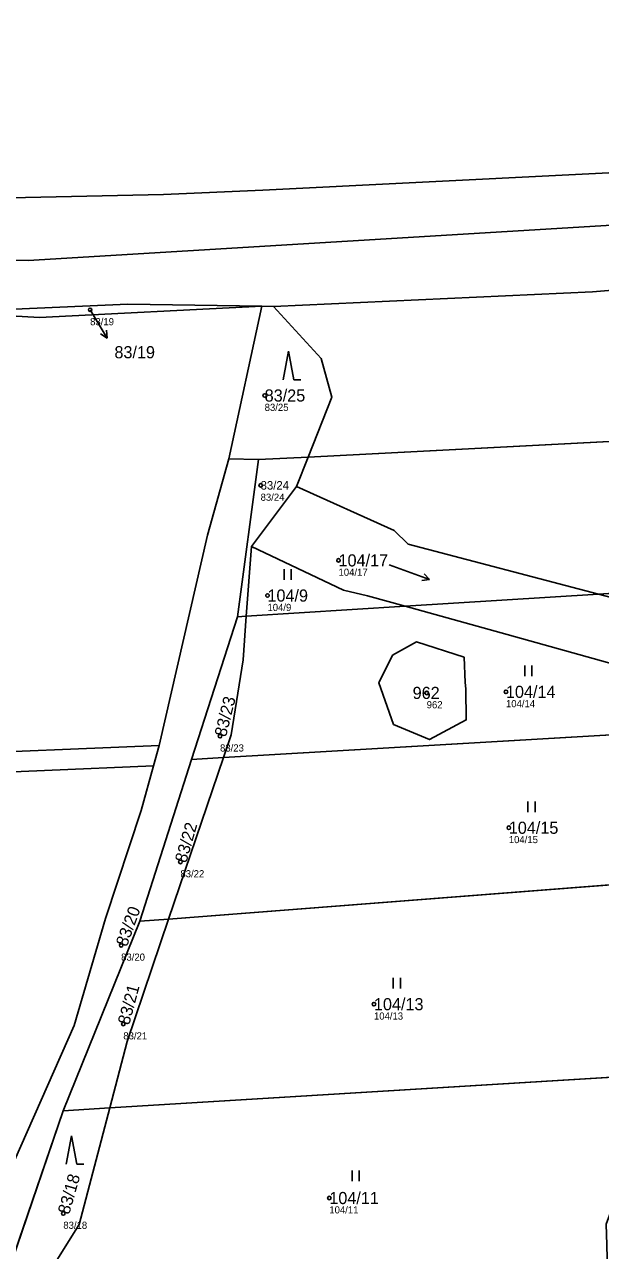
# Model space of a CAD drawing. Extents: x -734504 to -730695, y -1027923 to -1024502.
# Drawn here: x -731608.6 to -731527.8, y -1026155.5 to -1025983.6 of the extents above; entities that cross this region are included whole.
import ezdxf

# ---------------------------------------------------------------- set-up
doc = ezdxf.new("R2010")
doc.units = 0
for name, color, linetype in [('Definiční body', 7, 'Continuous'), ('Hranice parcel', 7, 'Continuous'), ('Parcelní čísla', 7, 'Continuous'), ('Polygon parcely', 7, 'Continuous'), ('Pop  PČ popisy', 7, 'Continuous'), ('Vnitřní kresba', 7, 'Continuous'), ('Značky kultur', 7, 'Continuous')]:
    doc.layers.add(name, color=color, linetype=linetype)

msp = doc.modelspace()

# ---------------------------------------------------------------- linework, layer by layer
at = {"layer": 'Definiční body'}
for centre in [(-731599.42, -1026023.65), (-731574.93, -1026035.66), (-731575.5, -1026048.26), (-731564.57, -1026058.78), (-731574.54, -1026063.71), (-731552.2, -1026077.36), (-731541.08, -1026077.21), (-731581.19, -1026083.42), (-731540.68, -1026096.27), (-731586.75, -1026101.06), (-731595.07, -1026112.75), (-731559.6, -1026121.01), (-731594.76, -1026123.79), (-731565.86, -1026148.19), (-731603.18, -1026150.35)]:
    msp.add_circle(centre, 0.25, dxfattribs=at)
at = {"layer": 'Hranice parcel'}
for p, q in [((-731579.95, -1026044.53), (-731575.33, -1026023.13)), ((-731575.33, -1026023.13), (-731573.67, -1026023.16)), ((-731568.83, -1026044.29), (-731476.12, -1026039.48)), ((-731575.78, -1026044.62), (-731579.95, -1026044.53)), ((-731578.73, -1026066.7), (-731575.78, -1026044.62)), ((-731568.83, -1026044.29), (-731575.78, -1026044.62)), ((-731570.47, -1026048.43), (-731568.83, -1026044.29)), ((-731576.8, -1026056.83), (-731570.47, -1026048.43)), ((-731577.51, -1026066.62), (-731576.8, -1026056.83)), ((-731528.11, -1026063.51), (-731466.76, -1026059.77)), ((-731528.11, -1026063.51), (-731555.24, -1026065.22)), ((-731577.51, -1026066.62), (-731555.24, -1026065.22)), ((-731585.19, -1026086.68), (-731578.73, -1026066.7)), ((-731577.51, -1026066.62), (-731578.73, -1026066.7)), ((-731577.96, -1026072.72), (-731577.51, -1026066.62)), ((-731579.64, -1026083.26), (-731577.96, -1026072.72)), ((-731580.71, -1026086.42), (-731482.31, -1026080.69)), ((-731580.71, -1026086.42), (-731579.64, -1026083.26)), ((-731590.53, -1026087.6), (-731589.71, -1026084.72)), ((-731592.44, -1026109.38), (-731585.19, -1026086.68)), ((-731588.4, -1026109.07), (-731580.71, -1026086.42)), ((-731580.71, -1026086.42), (-731585.19, -1026086.68)), ((-731506.7, -1026102.73), (-731588.4, -1026109.07)), ((-731603.21, -1026135.95), (-731592.44, -1026109.38)), ((-731594.22, -1026126.22), (-731588.4, -1026109.07)), ((-731588.4, -1026109.07), (-731592.44, -1026109.38)), ((-731596.66, -1026135.55), (-731594.22, -1026126.22)), ((-731519.15, -1026130.8), (-731596.66, -1026135.55)), ((-731596.66, -1026135.55), (-731603.21, -1026135.95)), ((-731603.21, -1026135.95), (-731612.63, -1026163.52))]:
    msp.add_line(p, q, dxfattribs=at)
for points in [[(-731897.94, -1025983.64), (-731862.07, -1025991.44), (-731847.22, -1025994.8), (-731827.82, -1025997.98), (-731799.13, -1026001.29), (-731775.22, -1026003.63), (-731763.84, -1026004.82), (-731742.5, -1026007.73), (-731730.75, -1026008.23), (-731698.59, -1026008.86), (-731662.59, -1026008.85), (-731619.31, -1026008.12), (-731589.11, -1026007.48), (-731575.19, -1026006.86), (-731508.93, -1026003.54), (-731470.15, -1026002.29), (-731442.98, -1026001.65), (-731406.79, -1026000.22), (-731383.28, -1026000.92)], [(-731473.47, -1026018.47), (-731481.39, -1026018.12), (-731500.93, -1026018.8), (-731528.93, -1026021.11), (-731573.67, -1026023.16)], [(-731619.6, -1026023.97), (-731594.13, -1026022.85), (-731575.33, -1026023.13)], [(-731575.33, -1026023.13), (-731606.51, -1026024.73), (-731619.6, -1026023.97)], [(-731573.67, -1026023.16), (-731567.02, -1026030.49), (-731565.51, -1026035.89), (-731568.83, -1026044.29)], [(-731589.71, -1026084.72), (-731582.94, -1026055.26), (-731579.95, -1026044.53)], [(-731528.11, -1026063.51), (-731554.81, -1026056.52), (-731556.78, -1026054.6), (-731570.47, -1026048.43)], [(-731555.24, -1026065.22), (-731560.52, -1026063.77), (-731563.87, -1026062.97), (-731576.8, -1026056.83)], [(-731471.3, -1026065.92), (-731479.74, -1026067.1), (-731492.82, -1026066.79), (-731519.69, -1026065.71), (-731528.11, -1026063.51)], [(-731555.24, -1026065.22), (-731541.77, -1026068.92), (-731524.83, -1026073.68), (-731511.48, -1026075.37), (-731503.25, -1026074.97), (-731482.31, -1026080.69)], [(-731546.8, -1026075.89), (-731546.95, -1026072.37), (-731553.62, -1026070.22), (-731556.98, -1026072.08), (-731558.92, -1026075.95), (-731556.85, -1026081.78), (-731551.82, -1026083.9), (-731546.64, -1026081.15), (-731546.71, -1026076.77), (-731546.8, -1026075.89)], [(-731589.71, -1026084.72), (-731621.46, -1026086.04), (-731697.6, -1026088.85), (-731731.22, -1026090.36)], [(-731590.53, -1026087.6), (-731621.14, -1026088.91), (-731698.05, -1026092.16), (-731731.15, -1026093.41)], [(-731630.9, -1026187.05), (-731624.84, -1026175.76), (-731612.94, -1026149.38), (-731601.66, -1026124.02), (-731597.25, -1026108.98), (-731592.25, -1026093.83), (-731590.53, -1026087.6)], [(-731608.08, -1026163.26), (-731600.95, -1026151.92), (-731596.66, -1026135.55)]]:
    msp.add_lwpolyline(points, dxfattribs=at)
at = {"layer": 'Polygon parcely'}
for points in [[(-731383.28, -1026000.92), (-731406.79, -1026000.22), (-731442.98, -1026001.65), (-731470.15, -1026002.29), (-731508.93, -1026003.54), (-731575.19, -1026006.86), (-731589.11, -1026007.48), (-731619.31, -1026008.12), (-731662.59, -1026008.85), (-731698.59, -1026008.86), (-731730.75, -1026008.23), (-731742.5, -1026007.73), (-731763.84, -1026004.82), (-731775.22, -1026003.63), (-731799.13, -1026001.29), (-731827.82, -1025997.98), (-731847.22, -1025994.8), (-731862.07, -1025991.44), (-731897.94, -1025983.64)], [(-731897.94, -1025983.64), (-731862.07, -1025991.44), (-731847.22, -1025994.8), (-731827.82, -1025997.98), (-731799.13, -1026001.29), (-731775.22, -1026003.63), (-731763.84, -1026004.82), (-731742.5, -1026007.73), (-731730.75, -1026008.23), (-731698.59, -1026008.86), (-731662.59, -1026008.85), (-731619.31, -1026008.12), (-731589.11, -1026007.48), (-731575.19, -1026006.86), (-731508.93, -1026003.54), (-731470.15, -1026002.29), (-731442.98, -1026001.65), (-731406.79, -1026000.22), (-731383.28, -1026000.92)], [(-731727.03, -1026023.83), (-731716.21, -1026023.81), (-731698.55, -1026023.77), (-731659.65, -1026023.51), (-731619.6, -1026023.97), (-731594.13, -1026022.85), (-731575.33, -1026023.13), (-731573.67, -1026023.16), (-731528.93, -1026021.11), (-731500.93, -1026018.8), (-731481.39, -1026018.12), (-731473.47, -1026018.47), (-731471.55, -1026018.36), (-731469.07, -1026018.22), (-731461.25, -1026017.78), (-731449.48, -1026016.71), (-731442.63, -1026016.08), (-731416.63, -1026016), (-731350.25, -1026014.24)]]:
    msp.add_lwpolyline(points, dxfattribs=at)
for points in [[(-731565.51, -1026035.89), (-731568.83, -1026044.29), (-731476.12, -1026039.48), (-731477.2, -1026037.15), (-731473.47, -1026018.47), (-731481.39, -1026018.12), (-731500.93, -1026018.8), (-731528.93, -1026021.11), (-731573.67, -1026023.16), (-731567.02, -1026030.49)], [(-731582.94, -1026055.26), (-731579.95, -1026044.53), (-731575.33, -1026023.13), (-731606.51, -1026024.73), (-731619.6, -1026023.97), (-731659.65, -1026023.51), (-731683.44, -1026026), (-731716.21, -1026023.81), (-731727.03, -1026023.83), (-731729.55, -1026023.95), (-731732.07, -1026023.98), (-731732.01, -1026034.57), (-731732.67, -1026049.28), (-731731.29, -1026087.21), (-731731.22, -1026090.36), (-731697.6, -1026088.85), (-731621.46, -1026086.04), (-731589.71, -1026084.72)], [(-731575.33, -1026023.13), (-731594.13, -1026022.85), (-731619.6, -1026023.97), (-731606.51, -1026024.73)], [(-731568.83, -1026044.29), (-731565.51, -1026035.89), (-731567.02, -1026030.49), (-731573.67, -1026023.16), (-731575.33, -1026023.13), (-731579.95, -1026044.53), (-731575.78, -1026044.62)], [(-731466.76, -1026059.77), (-731476.12, -1026039.48), (-731568.83, -1026044.29), (-731570.47, -1026048.43), (-731556.78, -1026054.6), (-731554.81, -1026056.52), (-731528.11, -1026063.51)], [(-731579.95, -1026044.53), (-731582.94, -1026055.26), (-731589.71, -1026084.72), (-731590.53, -1026087.6), (-731592.25, -1026093.83), (-731597.25, -1026108.98), (-731601.66, -1026124.02), (-731612.94, -1026149.38), (-731624.84, -1026175.76), (-731630.9, -1026187.05), (-731626.73, -1026188.13), (-731621.32, -1026178.95), (-731612.63, -1026163.52), (-731603.21, -1026135.95), (-731592.44, -1026109.38), (-731585.19, -1026086.68), (-731578.73, -1026066.7), (-731575.78, -1026044.62)], [(-731570.47, -1026048.43), (-731568.83, -1026044.29), (-731575.78, -1026044.62), (-731578.73, -1026066.7), (-731577.51, -1026066.62), (-731576.8, -1026056.83)], [(-731528.11, -1026063.51), (-731554.81, -1026056.52), (-731556.78, -1026054.6), (-731570.47, -1026048.43), (-731576.8, -1026056.83), (-731563.87, -1026062.97), (-731560.52, -1026063.77), (-731555.24, -1026065.22)], [(-731563.87, -1026062.97), (-731576.8, -1026056.83), (-731577.51, -1026066.62), (-731555.24, -1026065.22), (-731560.52, -1026063.77)], [(-731466.76, -1026059.77), (-731528.11, -1026063.51), (-731519.69, -1026065.71), (-731492.82, -1026066.79), (-731479.74, -1026067.1), (-731471.3, -1026065.92), (-731466.19, -1026061.01)], [(-731528.11, -1026063.51), (-731555.24, -1026065.22), (-731541.77, -1026068.92), (-731524.83, -1026073.68), (-731511.48, -1026075.37), (-731503.25, -1026074.97), (-731482.31, -1026080.69), (-731481.14, -1026080.63), (-731462.23, -1026074.08), (-731471.3, -1026065.92), (-731479.74, -1026067.1), (-731492.82, -1026066.79), (-731519.69, -1026065.71)], [(-731482.31, -1026080.69), (-731503.25, -1026074.97), (-731511.48, -1026075.37), (-731524.83, -1026073.68), (-731541.77, -1026068.92), (-731555.24, -1026065.22), (-731577.51, -1026066.62), (-731577.96, -1026072.72), (-731579.64, -1026083.26), (-731580.71, -1026086.42)], [(-731577.51, -1026066.62), (-731578.73, -1026066.7), (-731585.19, -1026086.68), (-731580.71, -1026086.42), (-731579.64, -1026083.26), (-731577.96, -1026072.72)], [(-731546.8, -1026075.89), (-731546.71, -1026076.77), (-731546.64, -1026081.15), (-731551.82, -1026083.9), (-731556.85, -1026081.78), (-731558.92, -1026075.95), (-731556.98, -1026072.08), (-731553.62, -1026070.22), (-731546.95, -1026072.37)], [(-731546.8, -1026075.89), (-731546.95, -1026072.37), (-731553.62, -1026070.22), (-731556.98, -1026072.08), (-731558.92, -1026075.95), (-731556.85, -1026081.78), (-731551.82, -1026083.9), (-731546.64, -1026081.15), (-731546.71, -1026076.77)], [(-731460.65, -1026079.08), (-731481.14, -1026080.63), (-731482.31, -1026080.69), (-731580.71, -1026086.42), (-731588.4, -1026109.07), (-731506.7, -1026102.73), (-731494.43, -1026093.08), (-731477.42, -1026087.59), (-731460.31, -1026080.16)], [(-731621.46, -1026086.04), (-731697.6, -1026088.85), (-731731.22, -1026090.36), (-731731.15, -1026093.41), (-731698.05, -1026092.16), (-731621.14, -1026088.91), (-731590.53, -1026087.6), (-731589.71, -1026084.72)], [(-731612.94, -1026149.38), (-731601.66, -1026124.02), (-731597.25, -1026108.98), (-731592.25, -1026093.83), (-731590.53, -1026087.6), (-731621.14, -1026088.91), (-731698.05, -1026092.16), (-731731.15, -1026093.41), (-731729.6, -1026159.46), (-731684.57, -1026173.9), (-731652.47, -1026184.25), (-731635.03, -1026188.69), (-731632.44, -1026189.52), (-731630.9, -1026187.05), (-731624.84, -1026175.76)], [(-731580.71, -1026086.42), (-731585.19, -1026086.68), (-731592.44, -1026109.38), (-731588.4, -1026109.07)], [(-731516.54, -1026115.92), (-731508.81, -1026104.39), (-731506.7, -1026102.73), (-731588.4, -1026109.07), (-731594.22, -1026126.22), (-731596.66, -1026135.55), (-731519.15, -1026130.8), (-731514.2, -1026117.57)], [(-731588.4, -1026109.07), (-731592.44, -1026109.38), (-731603.21, -1026135.95), (-731596.66, -1026135.55), (-731594.22, -1026126.22)], [(-731596.66, -1026135.55), (-731600.95, -1026151.92), (-731608.08, -1026163.26), (-731526.81, -1026158.57), (-731526.93, -1026154.74), (-731527.02, -1026151.87), (-731522.52, -1026139.82), (-731519.15, -1026130.8)], [(-731603.21, -1026135.95), (-731612.63, -1026163.52), (-731608.08, -1026163.26), (-731600.95, -1026151.92), (-731596.66, -1026135.55)]]:
    msp.add_lwpolyline(points, close=True, dxfattribs=at)
at = {"layer": 'Pop  PČ popisy'}
for p, q in [((-731599.42, -1026023.65), (-731598.57, -1026025.05)), ((-731598.57, -1026025.05), (-731597.02, -1026027.62)), ((-731597.02, -1026027.62), (-731597.97, -1026027.02)), ((-731597.02, -1026027.62), (-731597.11, -1026026.51))]:
    msp.add_line(p, q, dxfattribs=at)
at = {"layer": 'Vnitřní kresba'}
msp.add_lwpolyline([(-731739.28, -1026015), (-731608.1, -1026016.73), (-731451.32, -1026007.24), (-731364.57, -1026008.08), (-731305.14, -1026012.49), (-731265.75, -1026016.16), (-731249.68, -1026018.55), (-731220.78, -1026024.33), (-731170.26, -1026039.02), (-731127.3, -1026055.65), (-731100.51, -1026067.24), (-731081.11, -1026075.58), (-731070.69, -1026082.31), (-731018.8, -1026119.92), (-730984.01, -1026148.82)], dxfattribs=at)
at = {"layer": 'Značky kultur'}
for p, q in [((-731571.6, -1026029.46), (-731572.35, -1026033.46)), ((-731570.85, -1026033.46), (-731571.6, -1026029.46)), ((-731570.85, -1026033.46), (-731569.85, -1026033.46)), ((-731572.21, -1026061.51), (-731572.21, -1026060.01)), ((-731571.21, -1026061.51), (-731571.21, -1026060.01)), ((-731557.45, -1026059.42), (-731551.81, -1026061.47)), ((-731551.81, -1026061.47), (-731552.9, -1026061.61)), ((-731551.81, -1026061.47), (-731552.55, -1026060.67)), ((-731538.44, -1026075.01), (-731538.44, -1026073.51)), ((-731537.44, -1026075.01), (-731537.44, -1026073.51)), ((-731538, -1026094.07), (-731538, -1026092.57)), ((-731537, -1026094.07), (-731537, -1026092.57)), ((-731556.89, -1026118.81), (-731556.89, -1026117.31)), ((-731555.89, -1026118.81), (-731555.89, -1026117.31)), ((-731602.04, -1026139.45), (-731602.79, -1026143.45)), ((-731601.29, -1026143.45), (-731602.04, -1026139.45)), ((-731601.29, -1026143.45), (-731600.29, -1026143.45)), ((-731562.65, -1026145.84), (-731562.65, -1026144.34)), ((-731561.65, -1026145.84), (-731561.65, -1026144.34))]:
    msp.add_line(p, q, dxfattribs=at)

# ---------------------------------------------------------------- texts
at = {"layer": 'Definiční body'}
for s, p in [('83/19', (-731599.42, -1026025.81)), ('83/25', (-731574.93, -1026037.82)), ('83/24', (-731575.5, -1026050.42)), ('104/17', (-731564.57, -1026060.94)), ('104/9', (-731574.54, -1026065.87)), ('962', (-731552.2, -1026079.52)), ('104/14', (-731541.08, -1026079.37)), ('83/23', (-731581.19, -1026085.58)), ('104/15', (-731540.68, -1026098.43)), ('83/22', (-731586.75, -1026103.22)), ('83/20', (-731595.07, -1026114.91)), ('104/13', (-731559.6, -1026123.17)), ('83/21', (-731594.76, -1026125.95)), ('104/11', (-731565.86, -1026150.35)), ('83/18', (-731603.18, -1026152.51))]:
    msp.add_text(s, height=1, dxfattribs=at).set_placement(p)
at = {"layer": 'Parcelní čísla'}
for s, height, p in [('83/19', 1.7, (-731596.01, -1026030.44)), ('83/25', 1.7, (-731574.93, -1026036.51)), ('83/24', 1.19, (-731575.5, -1026048.85)), ('104/17', 1.7, (-731564.57, -1026059.63)), ('104/9', 1.7, (-731574.54, -1026064.56)), ('962', 1.7, (-731554.17, -1026078.21)), ('104/14', 1.7, (-731541.08, -1026078.06)), ('104/15', 1.7, (-731540.68, -1026097.12)), ('104/13', 1.7, (-731559.6, -1026121.86)), ('104/11', 1.7, (-731565.86, -1026149.04))]:
    msp.add_text(s, height=height, dxfattribs=at).set_placement(p)
for s, rotation, p in [('83/23', 76, (-731580.36, -1026083.62)), ('83/22', 74, (-731585.93, -1026101.29)), ('83/20', 70, (-731594.27, -1026113.04)), ('83/21', 75, (-731593.94, -1026124.01)), ('83/18', 74, (-731602.36, -1026150.58))]:
    msp.add_text(s, height=1.7, rotation=rotation, dxfattribs=at).set_placement(p)

doc.saveas('drawing.dxf')
